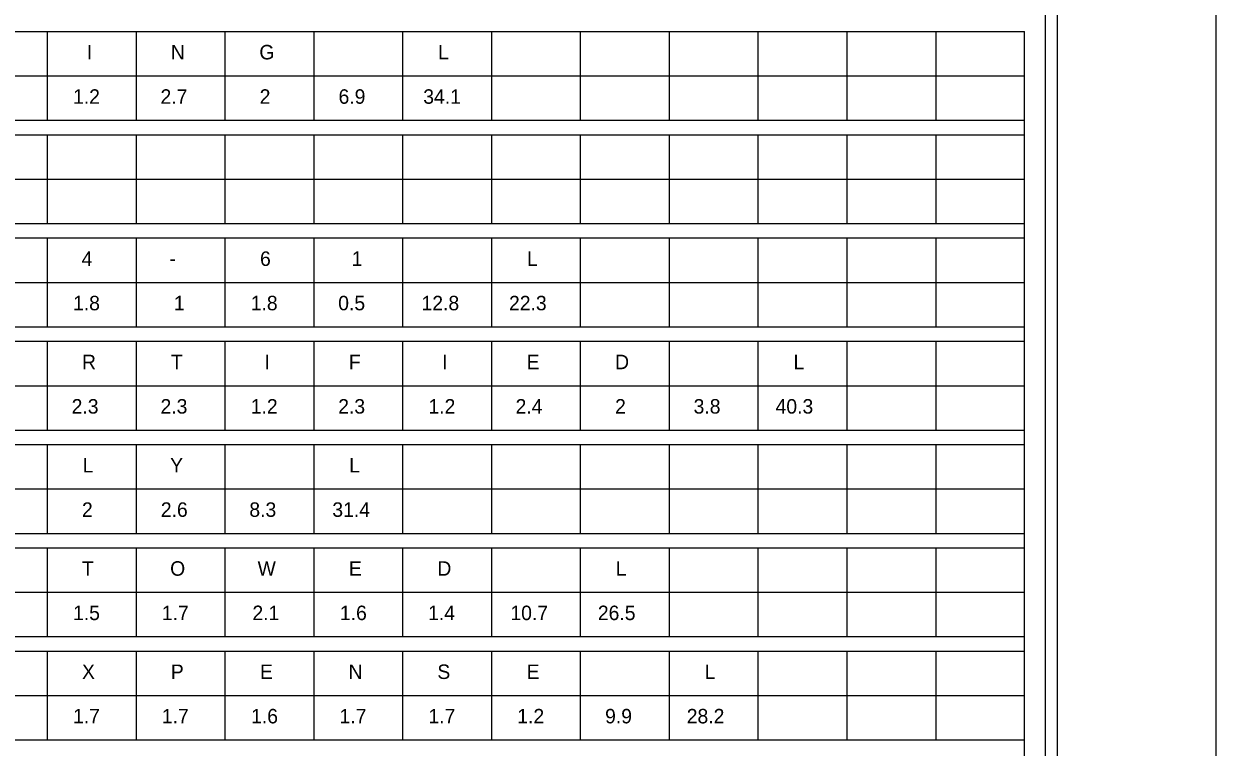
# Model space of a CAD drawing. Extents: x 17890484 to 17890754, y 17897495 to 17897992.
# Drawn here: x 17890605.25 to 17890645.65, y 17897547.83 to 17897572.31 of the extents above; entities that cross this region are included whole.
import ezdxf

# ---------------------------------------------------------------- set-up
doc = ezdxf.new("R2010")
doc.units = 0
for name, color, linetype in [('GSSign', 7, 'Continuous'), ('PlotBorder_dp', 7, 'Continuous'), ('SheetBorder_dp', 7, 'Continuous'), ('SheetLinesMisc1_dp', 7, 'Continuous'), ('SheetLinesMisc2_dp', 7, 'Continuous')]:
    doc.layers.add(name, color=color, linetype=linetype)

msp = doc.modelspace()

# ---------------------------------------------------------------- linework, layer by layer
at = {"layer": 'PlotBorder_dp'}
msp.add_lwpolyline([(17890483.9, 17897494.956), (17890645.649, 17897494.956), (17890645.649, 17897598.868), (17890483.9, 17897598.868)], close=True, dxfattribs=at)
at = {"layer": 'SheetBorder_dp'}
msp.add_line((17890640.258, 17897597.887), (17890640.258, 17897495.936), dxfattribs=at)
at = {"layer": 'SheetLinesMisc1_dp'}
for p, q in [((17890606.043, 17897572.057), (17890606.043, 17897569.051)), ((17890609.053, 17897572.057), (17890609.053, 17897569.051)), ((17890612.064, 17897572.057), (17890612.064, 17897569.051)), ((17890615.074, 17897572.057), (17890615.074, 17897569.051)), ((17890618.084, 17897572.057), (17890618.084, 17897569.051)), ((17890621.094, 17897572.057), (17890621.094, 17897569.051)), ((17890624.105, 17897572.057), (17890624.105, 17897569.051)), ((17890627.116, 17897572.057), (17890627.116, 17897569.051)), ((17890630.125, 17897572.057), (17890630.125, 17897569.051)), ((17890633.136, 17897572.057), (17890633.136, 17897569.051)), ((17890636.147, 17897572.057), (17890636.147, 17897569.051)), ((17890565.155, 17897570.553), (17890639.157, 17897570.554)), ((17890565.155, 17897569.051), (17890639.157, 17897569.051)), ((17890565.155, 17897568.561), (17890639.157, 17897568.561)), ((17890606.043, 17897568.561), (17890606.043, 17897565.554)), ((17890609.053, 17897568.561), (17890609.053, 17897565.554)), ((17890612.064, 17897568.561), (17890612.064, 17897565.554)), ((17890615.074, 17897568.561), (17890615.074, 17897565.554)), ((17890618.084, 17897568.561), (17890618.084, 17897565.554)), ((17890621.094, 17897568.561), (17890621.094, 17897565.554)), ((17890624.105, 17897568.561), (17890624.105, 17897565.554)), ((17890627.116, 17897568.561), (17890627.116, 17897565.554)), ((17890630.125, 17897568.561), (17890630.125, 17897565.554)), ((17890633.136, 17897568.561), (17890633.136, 17897565.554)), ((17890636.147, 17897568.561), (17890636.147, 17897565.554)), ((17890565.155, 17897567.057), (17890639.157, 17897567.057)), ((17890565.155, 17897565.554), (17890639.157, 17897565.554)), ((17890565.155, 17897565.064), (17890639.157, 17897565.064)), ((17890606.043, 17897565.064), (17890606.043, 17897562.057)), ((17890609.053, 17897565.064), (17890609.053, 17897562.057)), ((17890612.064, 17897565.064), (17890612.064, 17897562.057)), ((17890615.074, 17897565.064), (17890615.074, 17897562.057)), ((17890618.084, 17897565.064), (17890618.084, 17897562.057)), ((17890621.094, 17897565.064), (17890621.094, 17897562.057)), ((17890624.105, 17897565.064), (17890624.105, 17897562.057)), ((17890627.116, 17897565.064), (17890627.116, 17897562.057)), ((17890630.125, 17897565.064), (17890630.125, 17897562.057)), ((17890633.136, 17897565.064), (17890633.136, 17897562.057)), ((17890636.147, 17897565.064), (17890636.147, 17897562.057)), ((17890565.155, 17897563.561), (17890639.157, 17897563.561)), ((17890565.155, 17897562.057), (17890639.157, 17897562.057)), ((17890565.155, 17897561.567), (17890639.157, 17897561.567)), ((17890606.043, 17897561.567), (17890606.043, 17897558.561)), ((17890609.053, 17897561.567), (17890609.053, 17897558.561)), ((17890612.064, 17897561.567), (17890612.064, 17897558.561)), ((17890615.074, 17897561.567), (17890615.074, 17897558.561)), ((17890618.084, 17897561.567), (17890618.084, 17897558.561)), ((17890621.094, 17897561.567), (17890621.094, 17897558.561)), ((17890624.105, 17897561.567), (17890624.105, 17897558.561)), ((17890627.116, 17897561.567), (17890627.116, 17897558.561)), ((17890630.125, 17897561.567), (17890630.125, 17897558.561)), ((17890633.136, 17897561.567), (17890633.136, 17897558.561)), ((17890636.147, 17897561.567), (17890636.147, 17897558.561)), ((17890565.155, 17897560.064), (17890639.157, 17897560.064)), ((17890565.155, 17897558.561), (17890639.157, 17897558.561)), ((17890565.155, 17897558.07), (17890639.157, 17897558.07)), ((17890606.043, 17897558.07), (17890606.043, 17897555.064)), ((17890609.053, 17897558.07), (17890609.053, 17897555.064)), ((17890612.064, 17897558.07), (17890612.064, 17897555.064)), ((17890615.074, 17897558.07), (17890615.074, 17897555.064)), ((17890618.084, 17897558.07), (17890618.084, 17897555.064)), ((17890621.094, 17897558.07), (17890621.094, 17897555.064)), ((17890624.105, 17897558.07), (17890624.105, 17897555.064)), ((17890627.116, 17897558.07), (17890627.116, 17897555.064)), ((17890630.125, 17897558.07), (17890630.125, 17897555.064)), ((17890633.136, 17897558.07), (17890633.136, 17897555.064)), ((17890636.147, 17897558.07), (17890636.147, 17897555.064)), ((17890565.155, 17897556.568), (17890639.157, 17897556.568)), ((17890565.155, 17897555.064), (17890639.157, 17897555.064)), ((17890565.155, 17897554.574), (17890639.157, 17897554.574)), ((17890606.043, 17897554.574), (17890606.043, 17897551.568)), ((17890609.053, 17897554.574), (17890609.053, 17897551.568)), ((17890612.064, 17897554.574), (17890612.064, 17897551.568)), ((17890615.074, 17897554.574), (17890615.074, 17897551.568)), ((17890618.084, 17897554.574), (17890618.084, 17897551.568)), ((17890621.094, 17897554.574), (17890621.094, 17897551.568)), ((17890624.105, 17897554.574), (17890624.105, 17897551.568)), ((17890627.116, 17897554.574), (17890627.116, 17897551.568)), ((17890630.125, 17897554.574), (17890630.125, 17897551.568)), ((17890633.136, 17897554.574), (17890633.136, 17897551.568)), ((17890636.147, 17897554.574), (17890636.147, 17897551.568)), ((17890565.155, 17897553.071), (17890639.157, 17897553.071)), ((17890565.155, 17897551.568), (17890639.157, 17897551.568)), ((17890565.155, 17897551.078), (17890639.157, 17897551.078)), ((17890606.043, 17897551.078), (17890606.043, 17897548.072)), ((17890609.053, 17897551.078), (17890609.053, 17897548.072)), ((17890612.064, 17897551.078), (17890612.064, 17897548.072)), ((17890615.074, 17897551.078), (17890615.074, 17897548.072)), ((17890618.084, 17897551.078), (17890618.084, 17897548.072)), ((17890621.094, 17897551.078), (17890621.094, 17897548.072)), ((17890624.105, 17897551.078), (17890624.105, 17897548.072)), ((17890627.116, 17897551.078), (17890627.116, 17897548.072)), ((17890630.125, 17897551.078), (17890630.125, 17897548.072)), ((17890633.136, 17897551.078), (17890633.136, 17897548.072)), ((17890636.147, 17897551.078), (17890636.147, 17897548.072)), ((17890565.155, 17897549.574), (17890639.157, 17897549.574)), ((17890565.155, 17897548.072), (17890639.157, 17897548.072))]:
    msp.add_line(p, q, dxfattribs=at)
at = {"layer": 'SheetLinesMisc2_dp'}
for p, q in [((17890639.869, 17897504.15), (17890639.869, 17897597.807)), ((17890565.155, 17897572.057), (17890639.157, 17897572.057)), ((17890639.157, 17897506.112), (17890639.157, 17897572.057))]:
    msp.add_line(p, q, dxfattribs=at)

# ---------------------------------------------------------------- texts
at = {"layer": 'GSSign'}
for s, height, p in [('I', 0.49, (17890607.386, 17897571.111)), ('N', 0.49, (17890610.233, 17897571.111)), ('G', 0.49, (17890613.232, 17897571.111)), ('L', 0.49, (17890619.287, 17897571.111)), ('1.2', 0.4902, (17890606.919, 17897569.608)), ('2.7', 0.4902, (17890609.883, 17897569.608)), ('2', 0.49, (17890613.243, 17897569.608)), ('6.9', 0.4902, (17890615.915, 17897569.608)), ('34.1', 0.4902, (17890618.786, 17897569.608)), ('4', 0.49, (17890607.211, 17897564.119)), ('6', 0.49, (17890613.255, 17897564.119)), ('1', 0.49, (17890616.359, 17897564.119)), ('L', 0.49, (17890622.298, 17897564.119)), ('-', 0.49, (17890610.186, 17897564.119)), ('1.8', 0.4902, (17890606.919, 17897562.616)), ('1', 0.49, (17890610.338, 17897562.616)), ('1.8', 0.4902, (17890612.94, 17897562.616)), ('0.5', 0.4902, (17890615.904, 17897562.616)), ('12.8', 0.4902, (17890618.727, 17897562.616)), ('22.3', 0.4902, (17890621.691, 17897562.616)), ('R', 0.49, (17890607.223, 17897560.622)), ('T', 0.49, (17890610.233, 17897560.622)), ('I', 0.49, (17890613.407, 17897560.622)), ('F', 0.49, (17890616.265, 17897560.622)), ('I', 0.49, (17890619.427, 17897560.622)), ('E', 0.49, (17890622.286, 17897560.622)), ('D', 0.49, (17890625.285, 17897560.622)), ('L', 0.49, (17890631.329, 17897560.622)), ('2.3', 0.4902, (17890606.872, 17897559.119)), ('2.3', 0.4902, (17890609.883, 17897559.119)), ('1.2', 0.4902, (17890612.94, 17897559.119)), ('2.3', 0.4902, (17890615.904, 17897559.119)), ('1.2', 0.4902, (17890618.961, 17897559.119)), ('2.4', 0.4902, (17890621.913, 17897559.119)), ('2', 0.49, (17890625.285, 17897559.119)), ('3.8', 0.4902, (17890627.945, 17897559.119)), ('40.3', 0.4902, (17890630.722, 17897559.119)), ('L', 0.49, (17890607.246, 17897557.126)), ('Y', 0.49, (17890610.21, 17897557.126)), ('L', 0.49, (17890616.277, 17897557.126)), ('2', 0.49, (17890607.223, 17897555.623)), ('2.6', 0.4902, (17890609.894, 17897555.623)), ('8.3', 0.4902, (17890612.893, 17897555.623)), ('31.4', 0.4902, (17890615.705, 17897555.623)), ('T', 0.49, (17890607.223, 17897553.63)), ('O', 0.49, (17890610.21, 17897553.63)), ('W', 0.49, (17890613.173, 17897553.63)), ('E', 0.49, (17890616.265, 17897553.63)), ('D', 0.49, (17890619.264, 17897553.63)), ('L', 0.49, (17890625.308, 17897553.63)), ('1.5', 0.4902, (17890606.919, 17897552.127)), ('1.7', 0.4902, (17890609.93, 17897552.127)), ('2.1', 0.4902, (17890612.998, 17897552.127)), ('1.6', 0.4902, (17890615.962, 17897552.127)), ('1.4', 0.4902, (17890618.949, 17897552.127)), ('10.7', 0.4902, (17890621.738, 17897552.127)), ('26.5', 0.4902, (17890624.701, 17897552.127)), ('X', 0.49, (17890607.223, 17897550.134)), ('P', 0.49, (17890610.233, 17897550.134)), ('E', 0.49, (17890613.255, 17897550.134)), ('N', 0.49, (17890616.254, 17897550.134)), ('S', 0.49, (17890619.264, 17897550.134)), ('E', 0.49, (17890622.286, 17897550.134)), ('L', 0.49, (17890628.319, 17897550.134)), ('1.7', 0.4902, (17890606.919, 17897548.631)), ('1.7', 0.4902, (17890609.93, 17897548.631)), ('1.6', 0.4902, (17890612.952, 17897548.631)), ('1.7', 0.4902, (17890615.95, 17897548.631)), ('1.7', 0.4902, (17890618.961, 17897548.631)), ('1.2', 0.4902, (17890621.971, 17897548.631)), ('9.9', 0.4902, (17890624.946, 17897548.631)), ('28.2', 0.4902, (17890627.712, 17897548.631))]:
    msp.add_text(s, height=height, dxfattribs=at).set_placement(p)

doc.saveas('drawing.dxf')
